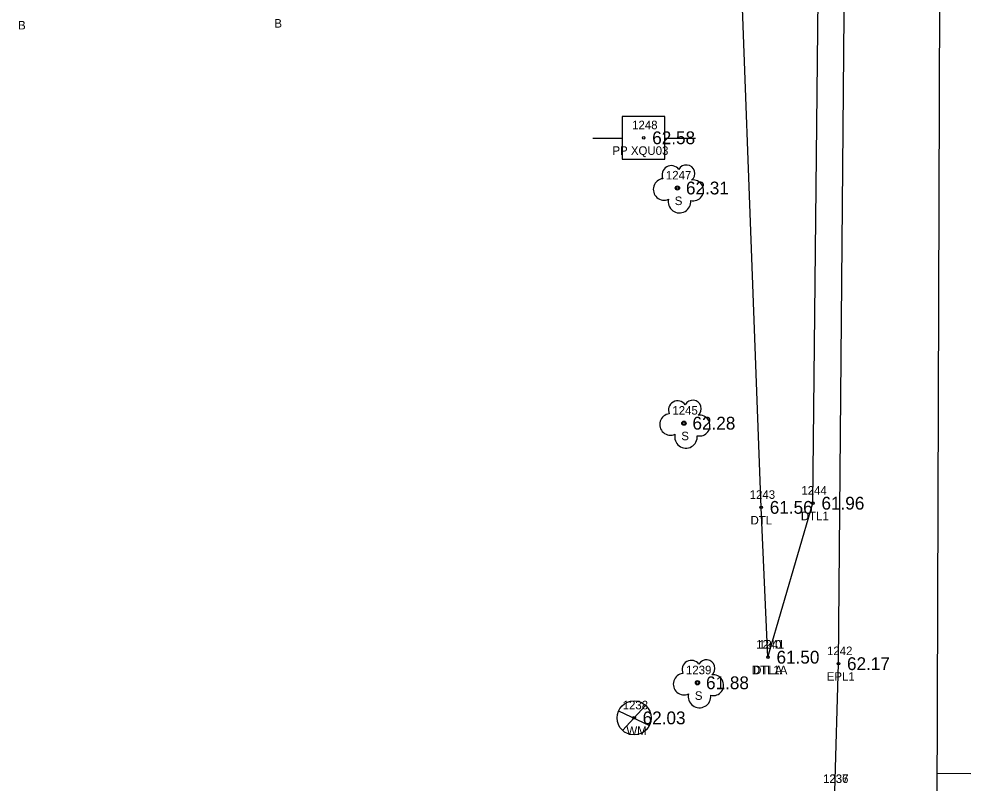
# Model space of a CAD drawing. Extents: x 2420113 to 2422887, y 845323 to 846653.
# Drawn here: x 2420852.8 to 2420964.3, y 845984.2 to 846073.7 of the extents above; entities that cross this region are included whole.
import ezdxf

# ---------------------------------------------------------------- set-up
doc = ezdxf.new("R2010")
doc.units = 0
for name, color, linetype in [('RD_EX_Bldg_txCode', 7, 'Continuous'), ('RD_EX_Driveway_txCode', 7, 'Continuous'), ('RD_EX_H2O', 7, 'Continuous'), ('RD_EX_H2O_txCode', 7, 'Continuous'), ('RD_EX_Road', 7, 'Continuous'), ('RD_EX_Road_txCode', 7, 'Continuous'), ('RD_EX_TX_H2O_ELEV', 7, 'Continuous'), ('RD_EX_TX_Road_ELEV', 7, 'Continuous'), ('RD_EX_TX_UT_ELEV', 7, 'Continuous'), ('RD_EX_TX_VEG_ELEV', 7, 'Continuous'), ('RD_EX_UT', 7, 'Continuous'), ('RD_EX_UT_txCode', 7, 'Continuous'), ('RD_EX_VEG', 7, 'Continuous'), ('RD_EX_VEG_txCode', 7, 'Continuous'), ('RD_HC_Cl', 7, 'Continuous'), ('RD_HC_Data_Tic', 7, 'Continuous'), ('RD_HC_Survey_ELEV', 7, 'Continuous'), ('RD_SMD_Locator', 7, 'Continuous')]:
    doc.layers.add(name, color=color, linetype=linetype)

msp = doc.modelspace()

# ---------------------------------------------------------------- linework, layer by layer
at = {"layer": 'RD_EX_H2O'}
for points in [[(2420940.5, 845999.01), (2420945.76, 846017.04), (2420946.69, 846105.79), (2420946.56, 846118.84), (2420942.41, 846122.08), (2420938.49, 846120.13)], [(2420940.5, 845999.01), (2420939.71, 846016.55), (2420936.38, 846105.33), (2420938.49, 846120.13)]]:
    msp.add_lwpolyline(points, dxfattribs=at)
at = {"layer": 'RD_EX_Road'}
msp.add_lwpolyline([(2420911.08, 845716.87), (2420926.22, 845723.04), (2420936.01, 845731.06), (2420942.67, 845742.11), (2420946.54, 845756.04), (2420945.56, 845775.49), (2420946.2, 845794.55), (2420948.14, 845835.31), (2420948.56, 845856.76), (2420948.65, 845897.5), (2420947.59, 845964.03), (2420948.31, 845983.28), (2420948.75, 845998.25), (2420949.7, 846105.56), (2420949.53, 846120.86), (2420949.28, 846141.3), (2420949.41, 846199.43)], dxfattribs=at)
at = {"layer": 'RD_EX_UT'}
for p, q in [((2420928.44, 846062.34), (2420923.44, 846062.34)), ((2420923.44, 846062.34), (2420923.44, 846057.34)), ((2420928.44, 846057.34), (2420928.44, 846062.34)), ((2420920.01, 846059.78), (2420923.48, 846059.78)), ((2420928.37, 846059.78), (2420932.01, 846059.78)), ((2420923.44, 846057.34), (2420928.44, 846057.34)), ((2420923, 845992.74), (2420926.63, 845991.02)), ((2420923.48, 845990.44), (2420926.15, 845993.34))]:
    msp.add_line(p, q, dxfattribs=at)
msp.add_circle((2420924.83, 845991.9), 2, dxfattribs=at)
at = {"layer": 'RD_EX_VEG'}
for centre in [(2420929.9, 846053.95), (2420930.66, 846026.41), (2420932.25, 845996.01)]:
    msp.add_circle(centre, 0.25, dxfattribs=at)
for centre, radius, start, end in [((2420929.18, 846055.49), 1.08, 34.9763, 204.756), ((2420930.94, 846055.65), 0.995, 308.7626, 152.0467), ((2420928.34, 846053.79), 1.26, 96.4518, 294.734), ((2420931.74, 846053.67), 1.22, 256.5667, 98.1046), ((2420930.14, 846052.35), 1.32, 166.8827, 5.7589), ((2420929.93, 846027.95), 1.08, 34.9763, 204.756), ((2420931.7, 846028.11), 0.995, 308.7626, 152.0467), ((2420929.09, 846026.25), 1.26, 96.4518, 294.734), ((2420932.49, 846026.13), 1.22, 256.5667, 98.1046), ((2420930.9, 846024.81), 1.32, 166.8827, 5.7589), ((2420931.53, 845997.56), 1.08, 34.9763, 204.756), ((2420933.29, 845997.71), 0.995, 308.7626, 152.0467), ((2420930.68, 845995.85), 1.26, 96.4518, 294.734), ((2420934.09, 845995.73), 1.22, 256.5667, 98.1046), ((2420932.49, 845994.41), 1.32, 166.8827, 5.7589)]:
    msp.add_arc(centre, radius, start, end, dxfattribs=at)
at = {"layer": 'RD_HC_Cl'}
msp.add_line((2420961.04, 846199.81), (2420959.23, 845699.82), dxfattribs=at)
at = {"layer": 'RD_HC_Data_Tic'}
msp.add_line((2420960.26, 845985.41), (2420964.26, 845985.4), dxfattribs=at)
at = {"layer": 'RD_SMD_Locator'}
for centre in [(2420925.95, 846059.83), (2420929.9, 846053.95), (2420930.66, 846026.41), (2420945.76, 846017.04), (2420939.71, 846016.55), (2420940.5, 845999.01), (2420940.5, 845999.01), (2420948.75, 845998.25), (2420932.25, 845996.01), (2420924.83, 845991.9)]:
    msp.add_circle(centre, 0.15, dxfattribs=at)

# ---------------------------------------------------------------- texts
at = {"layer": 'RD_EX_Bldg_txCode'}
for p in [(2420852.72, 846072.51), (2420882.72, 846072.73)]:
    msp.add_text('B', height=1, dxfattribs=at).set_placement(p)
at = {"layer": 'RD_EX_Driveway_txCode'}
msp.add_text('1236', height=1, dxfattribs=at).set_placement((2420946.94, 845984.28))
at = {"layer": 'RD_EX_H2O_txCode'}
for s, p in [('1243', (2420938.36, 846017.55)), ('1244', (2420944.41, 846018.04)), ('DTL1', (2420944.35, 846015.04)), ('DTL', (2420938.46, 846014.55)), ('1240', (2420939.12, 846000.01)), ('1241', (2420939.44, 846000.01)), ('DTL1A', (2420938.6, 845997.01)), ('DTLA', (2420938.77, 845997.01))]:
    msp.add_text(s, height=1, dxfattribs=at).set_placement(p)
at = {"layer": 'RD_EX_Road_txCode'}
for s, p in [('1242', (2420947.41, 845999.25)), ('EPL1', (2420947.38, 845996.25)), ('1237', (2420946.96, 845984.28))]:
    msp.add_text(s, height=1, dxfattribs=at).set_placement(p)
at = {"layer": 'RD_EX_TX_H2O_ELEV'}
for s, p in [('61.56', (2420940.71, 846015.8)), ('61.96', (2420946.76, 846016.29)), ('61.50', (2420941.5, 845998.26)), ('61.50', (2420941.5, 845998.26))]:
    msp.add_text(s, height=1.5, dxfattribs=at).set_placement(p)
at = {"layer": 'RD_EX_TX_Road_ELEV'}
msp.add_text('62.17', height=1.5, dxfattribs=at).set_placement((2420949.75, 845997.5))
at = {"layer": 'RD_EX_TX_UT_ELEV'}
msp.add_text('62.03', height=1.5, dxfattribs=at).set_placement((2420925.83, 845991.15))
at = {"layer": 'RD_EX_TX_VEG_ELEV'}
for s, p in [('62.31', (2420930.9, 846053.2)), ('62.28', (2420931.66, 846025.66)), ('61.88', (2420933.25, 845995.26))]:
    msp.add_text(s, height=1.5, dxfattribs=at).set_placement(p)
at = {"layer": 'RD_EX_UT_txCode'}
for s, p in [('1248', (2420924.6, 846060.83)), ('PP XQU03', (2420922.3, 846057.83)), ('1238', (2420923.49, 845992.9)), ('WM', (2420923.93, 845989.9))]:
    msp.add_text(s, height=1, dxfattribs=at).set_placement(p)
at = {"layer": 'RD_EX_VEG_txCode'}
for s, p in [('1247', (2420928.55, 846054.95)), ('S', (2420929.59, 846051.95)), ('1245', (2420929.31, 846027.41)), ('S', (2420930.35, 846024.41)), ('1239', (2420930.9, 845997.01)), ('S', (2420931.94, 845994.01))]:
    msp.add_text(s, height=1, dxfattribs=at).set_placement(p)
at = {"layer": 'RD_HC_Survey_ELEV'}
msp.add_text('62.58', height=1.5, dxfattribs=at).set_placement((2420926.95, 846059.08))

doc.saveas('drawing.dxf')
